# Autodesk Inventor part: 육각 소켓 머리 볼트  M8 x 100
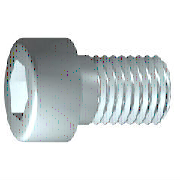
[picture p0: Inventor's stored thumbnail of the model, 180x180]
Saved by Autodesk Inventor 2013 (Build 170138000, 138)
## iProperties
IsCustomPart: 1
Created: 2012-02
Part Number: 육각 소켓 머리 볼트  M8 x 100
Material: 강철, 연강
Description: 6각 소켓 머리 캡 나사
Document SubType Name: Modeling
Standard: ISO 4762
Designer: mdu-01
Standard Revision: Fourth edition 2004-03-01
Standards Organization: ISO
Language: ko-KR
Size Designation: M8 x 12
Categories: <MemberInstance><Categories><Category DisplayName="조임쇠" InternalName="e4da775c-781d-43d5-af7c-5136215cf5a6" Mnemonic="FSTN"><Category DisplayName="볼트" InternalN
Density: 7.75 g/cm^3
Author: mdu-01
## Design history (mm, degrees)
sketch "스케치1"
  geometry: L1 (-2, 0)-(100, 0); L2 (100, 0)-(100, 4); L3 (100, 4)-(91.125, 4); L4 (91.125, 4)-(90.358, 4); L5 (90.358, 4)-(0, 4); L6 (0, 4)-(0, 6.5); L7 (0, 6.5)-(-8, 6.5); L8 (-8, 6.5)-(-8, 3.464); L9 (-8, 3.464)-(-4, 3.464); L10 (-4, 3.464)-(-2, 0); L11 (-29.6, 0)-(121.6, 0) reference; L12 (0, -1.3)-(0, 7.8) reference; L13 (91.125, 4)-(0, 4)
  constraints: 22 end point, 6 parallel, 2 collinear, 2 perpendicular, 1 horizontal, 1 point on line
  dimensions: "d1" = 8.875 distance from line of L3.end L2 (= GEL); "d2" = 0.76691 distance of L4.end L3.end (computed from GAL); "d3" = 8 distance between parallel lines of L8 L6 (= KOH); "d4" = 4 distance of L8.end L9.end (= INTI); "d5" = 60 deg angle of L10 L1; "d6" = 8 diameter of L3 L1 (= GD); "d7" = 8 diameter of L5 L1 (= BDM); "d8" = 6.9282 diameter of L9 L1 (= 1.1547 x SW); "d9" = 13 diameter of L7 L1 (= KOD); "d26" = 100 distance between parallel lines of L12 L2
revolve "본체" sketch "스케치1" stored, may be unused: angle "d10" = 90 deg
sketch "스케치2"
  geometry: L1 (0, -9.1)-(0, 9.1) reference; L2 (-9.1, 0)-(9.1, 0) reference; L3 (3.464, 0)-(1.732, -3); L4 (1.732, -3)-(-1.732, -3); L5 (-1.732, -3)-(-3.464, 0); L6 (-3.464, 0)-(-1.732, 3); L7 (-1.732, 3)-(1.732, 3); L8 (1.732, 3)-(3.464, 0); 2 further points
  constraints: 12 end point, 1 coincident, 1 horizontal alignment, 1 point on line, 12 other
extrude "슬롯" join sketch "스케치2" stored distance "d11" = 10; taper "d12" = 0 deg
workplane "Work Plane1"
fillet "Fillet2" dims "d30" = 0.1 (= R)
body "Solid1"
fillet "모깎기1" dims "d17" = 0.8 (= RR)
feature "스레드" dims "d13" = 20, "d14" = 0
chamfer "모따기1" distance "d15" = 0.76681 (= -0.5 x SPD + 0.5 x GD); stored, may be unused: second distance "d16" = 0.76681 (= GUL), angle "d27" = 45 deg
other parameters: "GD" = 8 [user parameter; used in 2 equation terms], "NLG" = 12 [user parameter], "GEL" = 8.875 [user parameter; used in 1 equation term], "KOD" = 13 [user parameter; used in 1 equation term], "KOH" = 8 [user parameter; used in 1 equation term], "INTI" = 4 [user parameter; used in 1 equation term], "GAL" = 0.76681 (= 0.61345 x PTC) [user parameter; used in 1 equation term], "GUL" = 0.76681 (= 0.61345 x PTC) [user parameter; used in 1 equation term], "BDM" = 8 (= NND) [user parameter; used in 1 equation term], "SW" = 6 [user parameter; used in 2 equation terms], "RR" = 0.8 [user parameter; used in 1 equation term], "SPD" = 6.46637 (= NND - 1.2269 x PTC) [user parameter; used in 1 equation term], "d19" = 0, "d28" = 0, "d29" = 0, "R" = 0.1 [user parameter; used in 1 equation term], "TOA" = 30 deg [user parameter], "GD1" = 6.46637 (= THREADDIA - 1.2269 x PTC) [user parameter], "THREADDIA" = 8 [user parameter; used in 1 equation term], "FAWI" = 45 deg [user parameter], "TPU" = 8 (computed from PTC) [user parameter], "PTC" = 1.25 [user parameter; used in 5 equation terms], "NND" = 8 [user parameter; used in 2 equation terms], "E0" = 6.93 (= 1.155 x SW) [user parameter]
